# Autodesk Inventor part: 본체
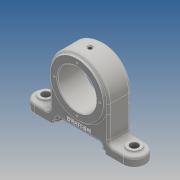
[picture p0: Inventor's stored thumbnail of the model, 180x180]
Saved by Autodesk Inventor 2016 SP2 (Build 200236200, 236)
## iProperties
Created: 2019-05
Part Number: 본체
Material: Generic
Document SubType Name: Modeling
Designer: EZ
Density: 1 g/cm^3
Appearance: Default
Mass: 169.297 g
Surface Area: 323.819 cm^2
Volume: 169.297 cm^3
Author: EZ
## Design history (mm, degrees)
sketch "스케치1"
  geometry: L1 (-75, -15)-(75, -15); L2 (75, -15)-(75, 15); L3 (75, 15)-(-75, 15); L4 (-75, 15)-(-75, -15); L5 (-75, -15)-(75, 15); L6 (75, -15)-(-75, 15); 1 further point
  constraints: 12 end point, 2 midpoint, 2 parallel, 1 horizontal, 1 perpendicular
  dimensions: "d0" = 150 distance of L3.end L2.end; "d1" = 30 distance of L2.end L1.end
extrude "돌출1" new body sketch "스케치1" distance "d2" = 12; taper "d3" = 0 deg
sketch "스케치2"
  geometry: L1 (120.991, 60)-(-120.991, 60); L2 (-75, 0)-(75, 0) reference; L3 (-75, 12)-(75, 12) reference; L4 (-40, 60)-(-40, 12); L5 (40, 60)-(40, 12); A1 r 40 centre (0, 60) between (40, 60) and (-40, 60); 2 further points
  constraints: 6 end point, 3 point on line, 2 point on circle, 2 tangent, 1 centre point, 1 coincident, 1 horizontal, 1 midpoint, 1 perpendicular, 1 vertical, 1 vertical alignment
  dimensions: "d4" = 60 distance between parallel lines of L2 L1; "d5" = 80 diameter of A1
extrude "돌출2" join sketch "스케치2" stored distance "d6" = 30; taper "d7" = 0 deg
sketch "스케치3"
  geometry: L1 (-75, 0)-(75, 0) reference; L2 (75, 0)-(75, 12) reference; L3 (40, 12)-(75, 12) reference; L4 (40, 12)-(40, 60) reference; L5 (-40, 60)-(-40, 12) reference; L6 (-75, 12)-(-40, 12) reference; L7 (-75, 0)-(-75, 12) reference; C1 r 36 at (0, 60); A1 r 40 centre (0, 60) between (40, 60) and (-40, 60) reference; 1 further point
  constraints: 1 centre point, 1 coincident
  dimensions: "d8" = 72 diameter of C1
extrude "돌출3" join sketch "스케치3" stored distance "d9" = 36; taper "d10" = 0 deg
sketch "스케치4"
  geometry: L1 (0, 0)-(150, 0) reference; L2 (150, 0)-(150, 12) reference; L3 (115, 12)-(150, 12) reference; L4 (115, 12)-(115, 60) reference; L5 (35, 60)-(35, 12) reference; L6 (0, 12)-(35, 12) reference; L7 (0, 0)-(0, 12) reference; L8 (39, 0)-(39, 4); L9 (39, 4)-(45, 4); L10 (45, 4)-(45, 10); L11 (45, 10)-(105, 10); L12 (105, 10)-(105, 4); L13 (105, 4)-(111, 4); L14 (111, 4)-(111, 0); C1 r 36 at (75, 60) reference; A1 r 40 centre (75, 60) between (115, 60) and (35, 60) reference; 1 further point
  constraints: 14 end point, 6 perpendicular, 4 point on line
  dimensions: "d11" = 72 distance between parallel lines of L14 L8; "d12" = 36 distance from line of L8 point (75, 0); "d13" = 4 distance between parallel lines of L1 L9; "d14" = 10 distance between parallel lines of L1 L11; "d15" = 60 distance between parallel lines of L12 L10; "d16" = 30 distance from line of point (75, 0) L10
extrude "돌출4" cut sketch "스케치4" stored distance "d17" = 36; taper "d18" = 0 deg
fillet "모깎기1" dims "d19" = 15
sketch "스케치6"
  geometry: L1 (-36, 15)-(-60, 15) reference; L2 (-36, 15)-(-36, -15) reference; L3 (-60, -15)-(-36, -15) reference; L4 (36, -15)-(60, -15) reference; L5 (36, -15)-(36, 15) reference; L6 (60, 15)-(36, 15) reference; C1 r 9 at (-60, 0); C2 r 9 at (60, 0); A1 r 15 centre (-60, 0) between (-60, 15) and (-60, -15) reference; A2 r 15 centre (60, 0) between (60, -15) and (60, 15) reference; 1 further point
  constraints: 2 centre point, 2 coincident
  dimensions: "d20" = 18 diameter of C1; "d21" = 18 diameter of C2
extrude "돌출5" join sketch "스케치6" distance "d22" = 3; taper "d23" = 0 deg
hole "구멍1" diameter "d26" = 11; stored, may be unused: countersink angle "d30" = 90 deg, drill point angle "d32" = 118 deg; dims "d24" = 10, "d25" = 10, "d27" = 6, "d28" = 4, "d29" = 2, "d31" = 8
hole "구멍2" diameter "d35" = 11; stored, may be unused: countersink angle "d39" = 90 deg, drill point angle "d41" = 118 deg; dims "d33" = 10, "d34" = 10, "d36" = 6, "d37" = 4, "d38" = 2, "d40" = 8
sketch "스케치7"
  geometry: L1 (-18, 96)-(-18, 24) reference; L2 (18, 24)-(18, 96) reference; L3 (-18, 60)-(18, 60); L4 (-18, 86)-(18, 86); L5 (-18, 86)-(-18, 60); L6 (18, 86)-(18, 60); 1 further point
  constraints: 8 end point, 3 midpoint, 3 point on line, 1 horizontal, 1 perpendicular, 1 vertical
  dimensions: "d42" = 52 diameter of L4 L3
revolve "회전1" sketch "스케치7" stored, may be unused: angle "d43" = 90 deg
fillet "모깎기2" dims "d44" = 6
sketch "스케치8" dims "d45" = 62
  geometry: C1 r 26 at (0, 0) reference; C2 r 36 at (0, 0) reference; 3 further points
  constraints: 2 vertical alignment, 1 coincident, 2 other
hole "구멍3" sketch "스케치8" at (0, 31) diameter "d46" = 3.242; stored, may be unused: countersink angle "d50" = 90 deg, drill point angle "d52" = 118 deg; dims "d47" = 6, "d48" = 4, "d49" = 2, "d51" = 8
node "작업 평면1"
sketch "스케치9"
  geometry: 2 further points
  constraints: 1 coincident
hole "구멍4" sketch "스케치9" at (0, 0) diameter "d57" = 4.917; stored, may be unused: countersink angle "d61" = 90 deg, drill point angle "d63" = 118 deg; dims "d58" = 8, "d59" = 7, "d60" = 1, "d62" = 10
hole "구멍5" diameter "d66" = 2; stored, may be unused: countersink angle "d70" = 90 deg, drill point angle "d72" = 118 deg; dims "d64" = 10, "d65" = 10, "d67" = 8, "d68" = 7, "d69" = 1, "d71" = 10
sketch "스케치11"
  geometry: C1 r 1.621 at (-31, 0) reference; C2 r 1.621 at (0, -31) reference; C3 r 1.621 at (31, 0) reference; C4 r 1.621 at (0, 31) reference; C5 r 36 at (0, 0) reference; 3 further points
  constraints: 2 vertical alignment, 1 other
hole "구멍6" sketch "스케치11" at (0, 26) diameter "d73" = 3; stored, may be unused: countersink angle "d77" = 90 deg, drill point angle "d79" = 118 deg; dims "d74" = 8, "d75" = 7, "d76" = 1, "d78" = 10
chamfer "모따기1" distance "d80" = 1; stored, may be unused: second distance "d81" = 2, angle "d82" = 45 deg
fillet "모깎기3" dims "d83" = 3
fillet "모깎기4" dims "d84" = 3
fillet "모깎기5" dims "d85" = 3
sketch "스케치13"
  geometry: L1 (9, 10)-(63, 10) reference; L2 (82, 9)-(96, 9) reference; L3 (73, 47.671)-(73, 18) reference; L4 (-1, 18)-(-1, 47.671) reference; L5 (-24, 9)-(-10, 9) reference; L6 (-24, 0)-(-24, 9) reference; L7 (-24, 0)-(0, 0) reference; L8 (0, 0)-(0, 4) reference; L9 (0, 4)-(3, 4) reference; L10 (3, 7)-(3, 4) reference; L11 (63, 13)-(9, 13) reference; L12 (69, 4)-(69, 7) reference; L13 (69, 4)-(72, 4) reference; L14 (72, 4)-(72, 0) reference; L15 (72, 0)-(96, 0) reference; L16 (96, 9)-(96, 0) reference; A1 r 9 centre (82, 18) between (73, 18) and (82, 9) reference; A2 r 39 centre (36, 60) between (-1, 47.671) and (73, 47.671) reference; A3 r 9 centre (-10, 18) between (-10, 9) and (-1, 18) reference; A4 r 6 centre (9, 7) between (9, 13) and (3, 7) reference; A5 r 6 centre (63, 7) between (69, 7) and (63, 13) reference; 2 further points
  constraints: 1 vertical alignment, 1 other
  dimensions: "d86" = 7 distance from line of L1 point (36, 17)
feature "엠보싱1" sketch "스케치13" dims "d0" = 150, "d1" = 30, "d87" = 0.5, "d88" = 0
fillet "모깎기6" dims "d89" = 3
node "솔리드1"
pattern_circular "원형 패턴1" dims angle "d54" = 360 deg
mirror "대칭1"
node "투영된 루프1"
node "투영된 루프2"
node "투영된 루프5"
node "투영된 루프6"
node "투영된 루프7"
node "투영된 루프8"
node "투영된 루프9"
